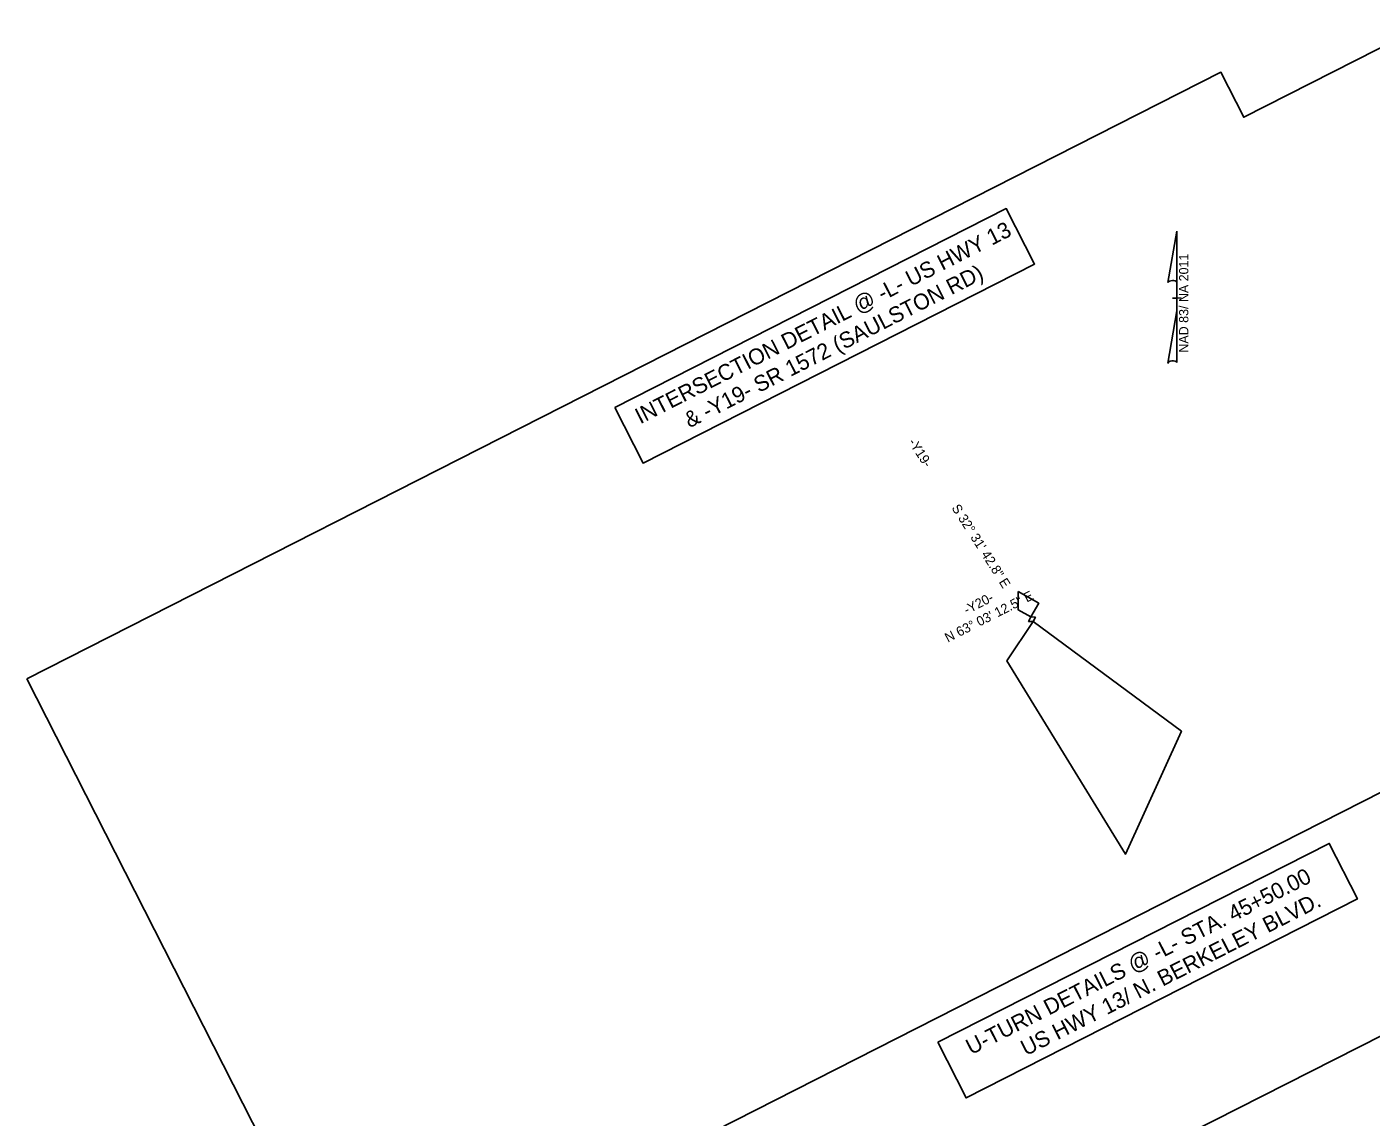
# Model space of a CAD drawing. Extents: x 2331355 to 2333079, y 611262 to 612828.
# Drawn here: x 2331355 to 2332342, y 611876 to 612677 of the extents above; entities that cross this region are included whole.
import ezdxf

# ---------------------------------------------------------------- set-up
doc = ezdxf.new("R2010")
doc.units = 0
for name, color, linetype in [('Default', 7, 'Continuous'), ('Prop Horizontal Alignment Direction Label', 7, 'Continuous'), ('Prop Horizontal Alignment Station Label', 7, 'Continuous'), ('Prop North Arrow NAD83 for Plan Sheets CELL', 7, 'Continuous'), ('Scratch_Level_1', 7, 'Continuous'), ('Sheet Plan CELL', 7, 'Continuous')]:
    doc.layers.add(name, color=color, linetype=linetype)

msp = doc.modelspace()

# ---------------------------------------------------------------- linework, layer by layer
at = {"layer": 'Default'}
for points in [[(2331786.82, 612397.73), (2332074.39, 612543.92), (2332095.16, 612503.06), (2331807.59, 612356.87)], [(2332024.02, 611931.12), (2332311.59, 612077.31), (2332332.36, 612036.45), (2332044.79, 611890.26)]]:
    msp.add_lwpolyline(points, close=True, dxfattribs=at)
at = {"layer": 'Prop North Arrow NAD83 for Plan Sheets CELL'}
for p, q in [((2332193.04, 612489.53), (2332199.63, 612527.38)), ((2332199.67, 612527.38), (2332199.63, 612527.38)), ((2332199.67, 612527.38), (2332199.63, 612527.38)), ((2332199.67, 612527.38), (2332199.67, 612488.82)), ((2332199.67, 612468.81), (2332199.67, 612489.95)), ((2332199.67, 612488.82), (2332199.67, 612489.9)), ((2332196.45, 612477.94), (2332196.41, 612477.94)), ((2332199.31, 612478.14), (2332196.45, 612477.94)), ((2332196.49, 612477.95), (2332202.92, 612478.39)), ((2332199.67, 612468.81), (2332192.96, 612430.23)), ((2332199.71, 612430.85), (2332199.67, 612468.81))]:
    msp.add_line(p, q, dxfattribs=at)
for centre, start_param, end_param in [((2332196.36, 612489.36), 0.176011, 2.867842), ((2332196.36, 612430.33), 0.160951, 3.101216)]:
    msp.add_ellipse(centre, major_axis=(3.4, 0.27), ratio=0.460709, start_param=start_param, end_param=end_param, dxfattribs=at)
at = {"layer": 'Scratch_Level_1'}
for points in [[(2332083.14, 612262.43), (2332098.26, 612253.81), (2332092.38, 612243.85), (2332090.77, 612240.42), (2332094.16, 612240.27), (2332202.98, 612159.67), (2332161.93, 612069.37), (2332074.8, 612211.4), (2332094.16, 612240.27), (2332095.8, 612243.55), (2332092.38, 612243.85), (2332083.19, 612248.87)], [(2331837.64, 611676.12), (2332704.77, 612115.95), (2332809.39, 611915.29), (2331984.65, 611496.71), (2331946.94, 611570.91), (2331905.9, 611550.04), (2331846.41, 611665.97)]]:
    msp.add_lwpolyline(points, close=True, dxfattribs=at)
at = {"layer": 'Sheet Plan CELL'}
for points in [[(2331354.84, 612198.14), (2332231.99, 612644.09), (2332248.84, 612610.95), (2332379.58, 612677.42), (2332421.89, 612594.18), (2332493.28, 612630.48), (2332529.96, 612558.33), (2332698.67, 612644.11), (2332840.79, 612364.62), (2331592.76, 611730.15)], [(2331592.76, 611730.15), (2332840.78, 612364.62), (2333078.69, 611896.65), (2331830.66, 611262.19)]]:
    msp.add_lwpolyline(points, close=True, dxfattribs=at)

# ---------------------------------------------------------------- texts
at = {"layer": 'Default'}
for s, p in [('INTERSECTION DETAIL @ -L- US HWY 13', (2331805.44, 612385.27)), ('& -Y19- SR 1572 (SAULSTON RD)', (2331841.57, 612382.37)), ('U-TURN DETAILS @ -L- STA. 45+50.00', (2332048.47, 611921.62)), ('US HWY 13/ N. BERKELEY BLVD.', (2332088.74, 611920.83))]:
    msp.add_text(s, height=11.6664, rotation=26.94752, dxfattribs=at).set_placement(p)
at = {"layer": 'Prop Horizontal Alignment Direction Label'}
for s, rotation, p in [('S 32%%d 31\' 42.8" E', 302.52855, (2332033.91, 612323.85)), ('N 63%%d 03\' 12.5" E', 26.94653, (2332031.4, 612224.79))]:
    msp.add_text(s, height=7, rotation=rotation, dxfattribs=at).set_placement(p)
at = {"layer": 'Prop Horizontal Alignment Station Label'}
for s, rotation, p in [('-Y19-', 302.77627, (2332002.11, 612372.2)), ('-Y20-', 26.94653, (2332045.26, 612245.41))]:
    msp.add_text(s, height=7, rotation=rotation, dxfattribs=at).set_placement(p)
at = {"layer": 'Prop North Arrow NAD83 for Plan Sheets CELL'}
msp.add_text('NAD 83/ NA 2011', height=6.845, rotation=90, dxfattribs=at).set_placement((2332208.12, 612438.01))

doc.saveas('drawing.dxf')
